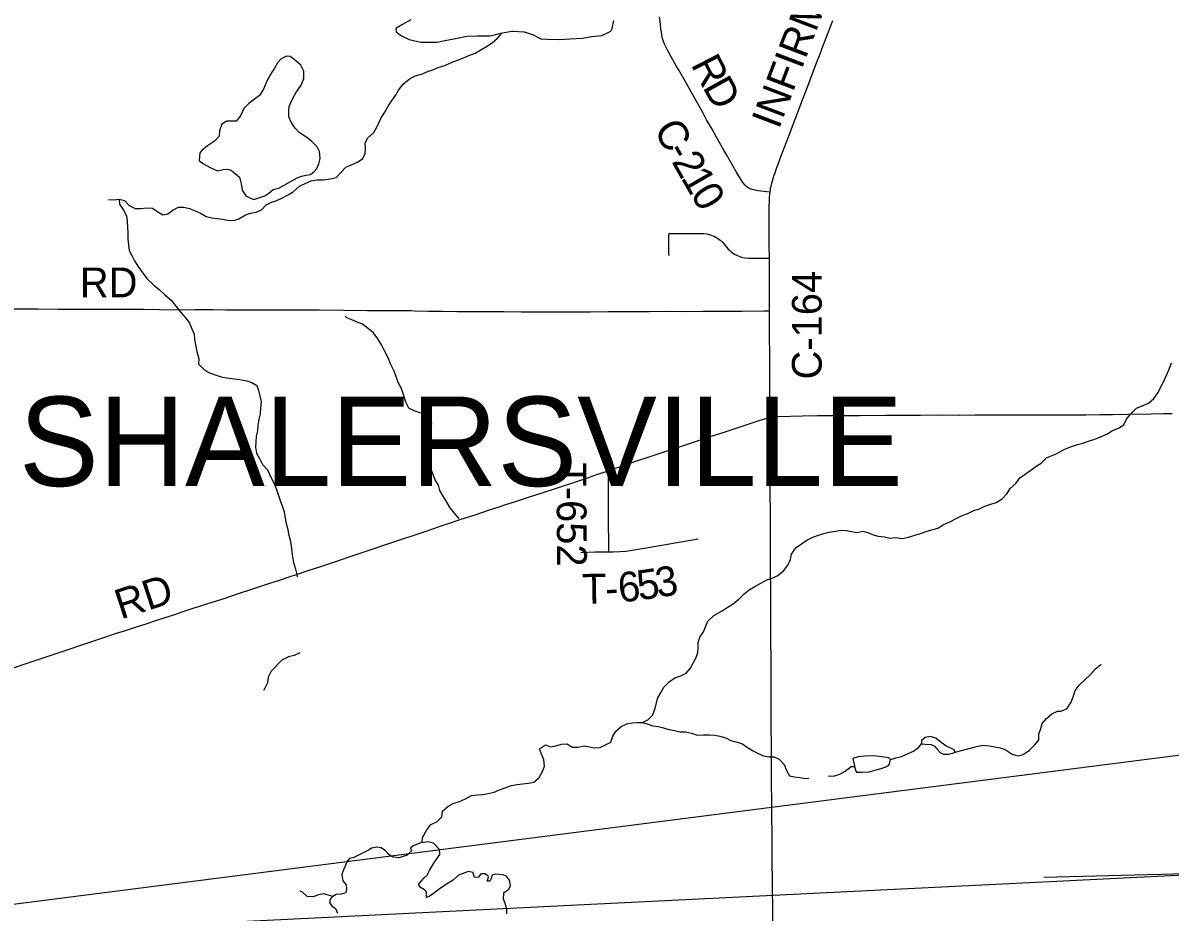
# Model space of a CAD drawing. Extents: x 0 to 34, y 0 to 22.
# Drawn here: x 5.643 to 7.83, y 17.616 to 19.311 of the extents above; entities that cross this region are included whole.
import ezdxf

# ---------------------------------------------------------------- set-up
doc = ezdxf.new("R2010")
doc.units = 0
for name, color, linetype in [('GM_X_County_Road', 7, 'Continuous'), ('GM_X_County_Road_Text', 7, 'Continuous'), ('GM_X_Minor_Lake', 7, 'Continuous'), ('GM_X_Minor_River', 7, 'Continuous'), ('GM_X_Township_Road', 7, 'Continuous'), ('GM_X_Township_Road_Text', 7, 'Continuous'), ('GM_X_Township_Text', 7, 'Continuous'), ('SH_Text', 7, 'Continuous')]:
    doc.layers.add(name, color=color, linetype=linetype)

msp = doc.modelspace()

# ---------------------------------------------------------------- linework, layer by layer
at = {"layer": 'GM_X_County_Road'}
for points in [[(7.0677, 18.9883), (7.0615, 18.9887), (7.0562, 18.9893), (7.0498, 18.9901), (7.0452, 18.9909), (7.0413, 18.9916), (7.0372, 18.9924), (7.0335, 18.9934), (7.0294, 18.9948), (7.026, 18.9967), (7.0234, 18.9984), (7.0201, 19.0014), (7.0159, 19.0065), (7.0123, 19.0115), (7.0091, 19.0167), (7.0043, 19.0251), (6.9859, 19.0574), (6.9795, 19.0685), (6.9719, 19.0818), (6.9655, 19.0933), (6.9569, 19.1084), (6.9467, 19.1264), (6.9391, 19.1403), (6.9235, 19.1684), (6.9141, 19.1853), (6.9025, 19.2057), (6.8932, 19.2219), (6.8882, 19.2303), (6.8822, 19.2406), (6.8725, 19.2579), (6.8663, 19.2705), (6.8642, 19.2756), (6.8628, 19.2811), (6.8612, 19.2877), (6.8603, 19.2931), (6.8595, 19.2991), (6.8585, 19.3083), (6.8569, 19.3227)], [(7.0677, 18.9883), (7.0681, 18.9916), (7.0687, 18.9956), (7.0695, 19), (7.0703, 19.0037), (7.0714, 19.0079), (7.0732, 19.0139), (7.075, 19.0194), (7.077, 19.0254), (7.0792, 19.0314), (7.0818, 19.0385), (7.0849, 19.0469), (7.087, 19.0525), (7.0953, 19.0743), (7.105, 19.0999), (7.1104, 19.1142), (7.1205, 19.1405), (7.1296, 19.1644), (7.1394, 19.1902), (7.1478, 19.2125), (7.1562, 19.2348), (7.1628, 19.2521), (7.1688, 19.268), (7.1755, 19.2854), (7.1872, 19.3154)], [(7.0662, 18.8626), (7.0661, 18.8861), (7.0659, 18.9169), (7.0658, 18.9363), (7.0659, 18.9459), (7.0659, 18.9555), (7.066, 18.9621), (7.0662, 18.9696), (7.0664, 18.9748), (7.0668, 18.9798), (7.0672, 18.9838), (7.0677, 18.9883)], [(7.0665, 18.7619), (7.0664, 18.799), (7.0662, 18.8427), (7.0662, 18.8626)], [(7.0674, 18.5587), (7.0673, 18.583), (7.0671, 18.631), (7.0669, 18.667), (7.0667, 18.7246), (7.0666, 18.7483), (7.0665, 18.7619)], [(6.7591, 18.4569), (6.7668, 18.4599), (6.7827, 18.4653), (6.8138, 18.4759), (6.8371, 18.4835), (6.8616, 18.4917), (6.8949, 18.5027), (6.9256, 18.513), (6.9516, 18.5216), (6.9799, 18.5307), (7.0201, 18.544), (7.0466, 18.5529), (7.0575, 18.5563), (7.0634, 18.5578), (7.0674, 18.5587)], [(7.0674, 18.5587), (7.0716, 18.5595), (7.0771, 18.5602), (7.0835, 18.5607), (7.1291, 18.5621), (7.1576, 18.5623), (7.1812, 18.5624), (7.2384, 18.5626), (7.2888, 18.5631), (7.3149, 18.5632), (7.3547, 18.5633), (7.3969, 18.5634), (7.428, 18.5633), (7.4584, 18.5635), (7.4708, 18.5634), (7.4987, 18.5634), (7.5347, 18.5636), (7.5689, 18.5637), (7.5888, 18.564), (7.6124, 18.564), (7.6509, 18.564), (7.6695, 18.5639), (7.6963, 18.5642), (7.7205, 18.5646), (7.7491, 18.565), (7.7945, 18.5657), (7.8175, 18.5661), (7.8342, 18.5665)], [(7.0731, 17.5947), (7.0727, 17.6245), (7.0726, 17.6352), (7.0725, 17.6478), (7.0722, 17.6785), (7.0719, 17.7095), (7.0715, 17.7689), (7.0712, 17.7939), (7.0709, 17.827), (7.0706, 17.86), (7.0704, 17.8782), (7.0702, 17.912), (7.07, 17.9364), (7.0698, 17.9667), (7.0696, 18.0001), (7.0695, 18.0272), (7.0694, 18.1022), (7.0693, 18.1295), (7.0691, 18.184), (7.0688, 18.232), (7.0686, 18.2645), (7.0685, 18.2999), (7.0682, 18.3495), (7.0681, 18.3774), (7.0679, 18.4134), (7.0678, 18.4367), (7.0677, 18.459), (7.0676, 18.4899), (7.0675, 18.5339), (7.0674, 18.5587)], [(5.6195, 18.0797), (5.653, 18.0911), (5.7214, 18.1139), (5.7652, 18.1282), (5.7858, 18.1352), (5.8235, 18.1478), (5.8347, 18.1515), (5.8577, 18.1589), (5.8778, 18.1654), (5.9003, 18.1727), (5.9346, 18.1839), (5.9428, 18.1866), (5.9698, 18.1955), (5.9715, 18.1961), (5.9739, 18.1968), (5.9786, 18.1984), (5.9844, 18.2002), (5.9862, 18.2008), (5.9919, 18.2024), (6.0038, 18.2063), (6.0268, 18.2138), (6.0539, 18.2228), (6.0793, 18.2311), (6.1122, 18.2421), (6.1322, 18.2487), (6.1487, 18.2542), (6.1683, 18.2604), (6.1872, 18.2666), (6.2131, 18.2753), (6.2378, 18.2836), (6.2689, 18.2942), (6.2954, 18.3031), (6.3485, 18.3207), (6.4081, 18.3406), (6.4268, 18.3472), (6.4404, 18.3518), (6.4562, 18.3572), (6.4727, 18.3627), (6.4905, 18.3684), (6.5052, 18.3732), (6.5182, 18.3774), (6.5305, 18.3818), (6.5511, 18.3886), (6.5658, 18.3936), (6.58, 18.398), (6.6073, 18.4065), (6.635, 18.4158), (6.6587, 18.4235), (6.7011, 18.4375), (6.72, 18.4436), (6.7335, 18.4484), (6.7591, 18.4569)]]:
    msp.add_lwpolyline(points, dxfattribs=at)
at = {"layer": 'GM_X_Minor_Lake'}
for p, q in [((6.1313, 18.9962), (6.166, 19.0155)), ((7.3745, 17.935), (7.3813, 17.932)), ((7.2256, 17.9084), (7.2307, 17.8857))]:
    msp.add_line(p, q, dxfattribs=at)
for points in [[(6.3825, 19.3171), (6.367, 19.3079), (6.3542, 19.3006), (6.355, 19.2942), (6.3649, 19.2863), (6.3797, 19.2796), (6.4017, 19.274), (6.432, 19.2743), (6.4543, 19.2786), (6.4713, 19.2818), (6.4894, 19.2857), (6.5091, 19.2862), (6.5337, 19.2864), (6.5545, 19.2915), (6.5753, 19.2955), (6.5783, 19.2955), (6.5987, 19.2938), (6.6147, 19.2889), (6.6303, 19.2807), (6.6428, 19.2801), (6.667, 19.2791), (6.6855, 19.2808), (6.7101, 19.2821), (6.7275, 19.2853), (6.7468, 19.2869), (6.7577, 19.2923), (6.7638, 19.295), (6.7664, 19.3003), (6.7697, 19.3155)], [(6.166, 19.0155), (6.1743, 19.0189), (6.1834, 19.0205), (6.1913, 19.0221), (6.1981, 19.0275), (6.2037, 19.0332), (6.2071, 19.0423), (6.2096, 19.0526), (6.2084, 19.0659), (6.2038, 19.0749), (6.1942, 19.0851), (6.1843, 19.0926), (6.1695, 19.1023), (6.1619, 19.1106), (6.1542, 19.122), (6.1503, 19.1322), (6.1499, 19.1432), (6.151, 19.1519), (6.1569, 19.1664), (6.1636, 19.1778), (6.1734, 19.1923), (6.1789, 19.2048), (6.1784, 19.2192), (6.1731, 19.2306), (6.1597, 19.2419), (6.1525, 19.2467), (6.1453, 19.2474), (6.1355, 19.2424), (6.1287, 19.2348), (6.1224, 19.2237), (6.1175, 19.2173), (6.1082, 19.2001), (6.1019, 19.1849), (6.094, 19.1723), (6.0846, 19.1658), (6.0737, 19.1574), (6.0643, 19.1478), (6.058, 19.1337), (6.0497, 19.1238), (6.0316, 19.1237), (6.0225, 19.1179), (6.0181, 19.105), (6.017, 19.0951), (6.0084, 19.0856), (5.9952, 19.0764), (5.9843, 19.0679), (5.9806, 19.0634), (5.9788, 19.0489), (5.986, 19.0429), (6.0016, 19.0347), (6.0141, 19.0287), (6.0247, 19.0318), (6.0334, 19.0319), (6.0402, 19.0304), (6.0448, 19.0267), (6.0559, 19.0169), (6.0594, 19.0044), (6.061, 18.9919), (6.0686, 18.9806), (6.0834, 18.9746), (6.1042, 18.9812), (6.1117, 18.9862), (6.1204, 18.9931), (6.1313, 18.9962)], [(7.3813, 17.932), (7.3855, 17.9267), (7.3924, 17.9195), (7.3985, 17.9166), (7.4072, 17.917), (7.4159, 17.9186), (7.4204, 17.9205), (7.4185, 17.9251), (7.4029, 17.9325), (7.3941, 17.9389), (7.3839, 17.9472), (7.3732, 17.9501), (7.363, 17.9485), (7.3563, 17.9428), (7.3563, 17.9363), (7.3635, 17.9356), (7.3745, 17.935)], [(7.2307, 17.8857), (7.2322, 17.8827), (7.2349, 17.8823), (7.2417, 17.8824), (7.2564, 17.8832), (7.2697, 17.8868), (7.2791, 17.8895), (7.2885, 17.8926), (7.2934, 17.8953), (7.2953, 17.8979), (7.2975, 17.9063), (7.2941, 17.9097), (7.2801, 17.9119), (7.2645, 17.9136), (7.2479, 17.9131), (7.2358, 17.9115), (7.2256, 17.9084)], [(6.3444, 17.7223), (6.3395, 17.7268), (6.3341, 17.7321), (6.3261, 17.7381), (6.3182, 17.7392), (6.3076, 17.7376), (6.3034, 17.7345), (6.2966, 17.731), (6.2895, 17.7276), (6.2737, 17.7195), (6.2657, 17.7175), (6.2616, 17.7133), (6.2586, 17.7065), (6.2542, 17.6962), (6.2512, 17.6874), (6.252, 17.6829), (6.2528, 17.6753), (6.2593, 17.6678), (6.2601, 17.6598), (6.259, 17.6526), (6.25, 17.6495), (6.2405, 17.6494), (6.2341, 17.6456), (6.2288, 17.6403), (6.2274, 17.6334), (6.232, 17.6274), (6.2392, 17.6225), (6.2431, 17.6138)], [(6.5655, 17.6125), (6.5658, 17.6212), (6.5616, 17.6341), (6.5596, 17.6401), (6.5599, 17.6515), (6.561, 17.6538), (6.5686, 17.6588), (6.5727, 17.6656), (6.5707, 17.6762), (6.565, 17.6842), (6.5578, 17.6868), (6.5449, 17.6882), (6.537, 17.6862), (6.5362, 17.6809), (6.5336, 17.6748), (6.5283, 17.6744), (6.5309, 17.6824), (6.5298, 17.6846), (6.5237, 17.6888), (6.5173, 17.6883), (6.515, 17.6864), (6.5116, 17.6822), (6.5041, 17.6814), (6.5025, 17.6856), (6.5017, 17.6913), (6.4919, 17.6931), (6.4858, 17.6904), (6.4734, 17.6857), (6.4632, 17.6762), (6.4504, 17.6689), (6.435, 17.6581), (6.4259, 17.6512), (6.4173, 17.6455), (6.4124, 17.6432), (6.4127, 17.6545), (6.4089, 17.6579), (6.4013, 17.6624), (6.3974, 17.6681), (6.4076, 17.6803), (6.4139, 17.686), (6.418, 17.6948), (6.4251, 17.707), (6.4322, 17.7173), (6.4379, 17.7253), (6.437, 17.7348), (6.426, 17.7468), (6.4157, 17.7498), (6.4017, 17.7478), (6.3874, 17.742), (6.3818, 17.7374), (6.3837, 17.7325), (6.3754, 17.7244), (6.366, 17.7209), (6.3592, 17.719), (6.3493, 17.7204), (6.3444, 17.7223)]]:
    msp.add_lwpolyline(points, dxfattribs=at)
at = {"layer": 'GM_X_Minor_River'}
for points in [[(5.806, 18.9744), (5.8162, 18.9737), (5.8264, 18.9749), (5.8367, 18.9724), (5.8458, 18.9626), (5.8572, 18.957), (5.8678, 18.957), (5.8792, 18.9586), (5.8898, 18.958), (5.9001, 18.9508), (5.9096, 18.9448), (5.9194, 18.9472), (5.9292, 18.9537), (5.9397, 18.9599), (5.9496, 18.9599), (5.9609, 18.957), (5.9704, 18.9533), (5.9814, 18.9484), (5.9925, 18.9417), (6.0035, 18.9395), (6.0133, 18.9381), (6.0235, 18.937), (6.0334, 18.9348), (6.0451, 18.9341), (6.055, 18.9372), (6.0674, 18.9449), (6.0772, 18.948), (6.0878, 18.9504), (6.098, 18.9543), (6.107, 18.9642), (6.1172, 18.9692), (6.127, 18.9723), (6.1379, 18.9773), (6.1477, 18.9827), (6.1583, 18.9892), (6.1707, 18.9996), (6.1827, 19.0057), (6.1925, 19.0096), (6.2035, 19.0116), (6.2164, 19.0117), (6.2292, 19.0137), (6.2406, 19.016), (6.2499, 19.0263), (6.259, 19.0359), (6.2707, 19.0409), (6.2812, 19.0452), (6.2914, 19.0524), (6.2958, 19.062), (6.2965, 19.0715), (6.2953, 19.0821), (6.3005, 19.0916), (6.3118, 19.1023), (6.3185, 19.1137), (6.3264, 19.1301), (6.3331, 19.1408), (6.3391, 19.1507), (6.3454, 19.161), (6.3533, 19.1724), (6.3593, 19.1827), (6.3679, 19.1945), (6.3795, 19.2037), (6.3912, 19.2099), (6.4048, 19.2141), (6.4146, 19.2184), (6.4248, 19.2215), (6.435, 19.2261), (6.4475, 19.23), (6.458, 19.2347), (6.4716, 19.2397), (6.4818, 19.2439), (6.4931, 19.2486), (6.5052, 19.2532), (6.5161, 19.2597), (6.5271, 19.2659), (6.5376, 19.2732), (6.5481, 19.2816), (6.5567, 19.2919)], [(5.8264, 18.9749), (5.8269, 18.9655), (5.8349, 18.9541), (5.8403, 18.9432), (5.8415, 18.9326), (5.8424, 18.9216), (5.8428, 18.911), (5.8433, 18.8988), (5.8445, 18.8878), (5.8457, 18.8772), (5.8504, 18.8674), (5.8557, 18.8576), (5.8634, 18.8455), (5.8707, 18.8357), (5.8791, 18.8236), (5.8924, 18.8112), (5.9027, 18.8029), (5.9138, 18.7928), (5.926, 18.7823), (5.9355, 18.7702), (5.9447, 18.7585), (5.9538, 18.7483), (5.9604, 18.7385), (5.965, 18.7279), (5.9696, 18.7177), (5.9704, 18.7071), (5.9744, 18.6844), (5.9783, 18.6708), (5.9776, 18.6601), (5.9879, 18.6507), (5.9978, 18.6447), (6.0099, 18.6399), (6.0209, 18.6362), (6.0312, 18.634), (6.0463, 18.6322), (6.0562, 18.6308), (6.0698, 18.6286), (6.0793, 18.6253), (6.0892, 18.6196), (6.0923, 18.6098), (6.0946, 18.6), (6.097, 18.5886), (6.0963, 18.5765), (6.0953, 18.5658), (6.0931, 18.5556), (6.0909, 18.5442), (6.0902, 18.5335), (6.0877, 18.5229), (6.087, 18.5119), (6.0867, 18.502), (6.0883, 18.4907), (6.0941, 18.4805), (6.0998, 18.4688), (6.1094, 18.4586), (6.1155, 18.445), (6.1209, 18.4352), (6.1263, 18.4212), (6.1302, 18.4102), (6.1333, 18.4004), (6.1379, 18.3886), (6.141, 18.3788), (6.1442, 18.3591), (6.1473, 18.3477), (6.1501, 18.3345), (6.1524, 18.3247), (6.1544, 18.314), (6.156, 18.3034), (6.1568, 18.2928), (6.1592, 18.2822), (6.1627, 18.2694), (6.165, 18.2591), (6.1658, 18.255)], [(6.4746, 18.3654), (6.465, 18.3767), (6.4574, 18.3865), (6.4512, 18.3975), (6.4443, 18.4088), (6.4382, 18.4194), (6.4351, 18.4296), (6.4289, 18.4398), (6.4251, 18.4496), (6.4212, 18.4598), (6.4143, 18.4704), (6.4078, 18.4814), (6.4055, 18.4923), (6.408, 18.503), (6.4117, 18.5132), (6.4169, 18.5247), (6.4195, 18.5364), (6.4228, 18.5471), (6.4186, 18.5573), (6.4098, 18.5671), (6.3996, 18.5674), (6.3889, 18.5711), (6.3787, 18.5767), (6.3733, 18.5877), (6.3683, 18.6047), (6.3644, 18.6149), (6.3586, 18.6255), (6.3544, 18.6365), (6.3501, 18.6482), (6.3436, 18.6607), (6.3397, 18.6724), (6.3332, 18.6845), (6.327, 18.6973), (6.3198, 18.7086), (6.3113, 18.72), (6.3018, 18.7278), (6.2908, 18.7365), (6.2802, 18.7402), (6.2703, 18.7447), (6.2608, 18.7484), (6.2574, 18.7518)], [(7.6132, 18.4891), (7.6286, 18.4973), (7.6407, 18.5027), (7.6535, 18.507), (7.6641, 18.5094), (7.6765, 18.5142), (7.6867, 18.5173), (7.6973, 18.5216), (7.7097, 18.5267), (7.7203, 18.5336), (7.7319, 18.5383), (7.7421, 18.5449), (7.7469, 18.5552), (7.7547, 18.5652), (7.7664, 18.5763), (7.7773, 18.581), (7.789, 18.5861), (7.7995, 18.5946), (7.8077, 18.6061), (7.8129, 18.6171), (7.8181, 18.6278), (7.824, 18.6408), (7.8284, 18.6507), (7.8332, 18.6629)], [(7.2958, 18.3288), (7.3075, 18.3297), (7.3204, 18.3279), (7.3313, 18.3302), (7.3438, 18.3341), (7.3547, 18.3372), (7.3649, 18.3415), (7.3763, 18.3446), (7.3872, 18.3477), (7.3978, 18.3539), (7.4102, 18.3597), (7.4223, 18.3658), (7.434, 18.3716), (7.4449, 18.3759), (7.4558, 18.3816), (7.4668, 18.3847), (7.477, 18.3898), (7.4868, 18.3925), (7.4989, 18.3967), (7.5098, 18.4033), (7.5199, 18.414), (7.5255, 18.4235), (7.5364, 18.4331), (7.5439, 18.4437), (7.5541, 18.4507), (7.5646, 18.4583), (7.5748, 18.4656), (7.5846, 18.4717), (7.5947, 18.4817), (7.6132, 18.4891)], [(6.4044, 17.7481), (6.4051, 17.758), (6.4133, 17.7725), (6.4211, 17.7828), (6.4321, 17.7874), (6.4418, 17.7974), (6.4429, 17.808), (6.453, 17.8172), (6.4632, 17.8226), (6.4753, 17.8265), (6.487, 17.8315), (6.4983, 17.8376), (6.5097, 17.8392), (6.5195, 17.8397), (6.5304, 17.8417), (6.5418, 17.8444), (6.552, 17.849), (6.5746, 17.8568), (6.5856, 17.8588), (6.5958, 17.8604), (6.6067, 17.8612), (6.617, 17.8632), (6.6271, 17.872), (6.6334, 17.8838), (6.6375, 17.8937), (6.6363, 17.9058), (6.6321, 17.9164), (6.6278, 17.9266), (6.6395, 17.9343), (6.649, 17.9306), (6.6592, 17.9329), (6.6698, 17.9357), (6.6803, 17.9365), (6.691, 17.9301), (6.7008, 17.9302), (6.7129, 17.9326), (6.7232, 17.9304), (6.7326, 17.9286), (6.7436, 17.9294), (6.764, 17.9398), (6.768, 17.9508), (6.7733, 17.9603), (6.7834, 17.9695), (6.7944, 17.9745), (6.8046, 17.9765), (6.8144, 17.9773), (6.8246, 17.9774), (6.8344, 17.9824), (6.8442, 17.992), (6.8482, 18.0045), (6.8534, 18.0243), (6.8601, 18.035), (6.865, 18.0445), (6.8751, 18.0548), (6.886, 18.0621), (6.8974, 18.066), (6.9075, 18.071), (6.9158, 18.0809), (6.9214, 18.0912), (6.9266, 18.1011), (6.9299, 18.1106), (6.9302, 18.1205), (6.9305, 18.1299), (6.9335, 18.1398), (6.9406, 18.1501), (6.9443, 18.1596), (6.9488, 18.1703), (6.9604, 18.181), (6.9763, 18.1898), (6.9861, 18.1964), (6.997, 18.2033), (7.0086, 18.2128), (7.018, 18.2224), (7.0278, 18.2301), (7.0387, 18.2362), (7.05, 18.2427), (7.0613, 18.2489), (7.0719, 18.2524), (7.0821, 18.2574), (7.0938, 18.267), (7.1016, 18.2769), (7.1065, 18.2876), (7.1083, 18.2982), (7.1176, 18.3108), (7.1274, 18.3177), (7.1376, 18.3246), (7.1478, 18.3296), (7.158, 18.3338), (7.17, 18.3377), (7.1799, 18.3397), (7.1927, 18.3421), (7.2025, 18.344), (7.2124, 18.343), (7.223, 18.3415), (7.2329, 18.3393), (7.2442, 18.3421), (7.2537, 18.3395), (7.2632, 18.3354), (7.273, 18.3324), (7.2855, 18.3314), (7.2958, 18.3288)], [(6.1711, 18.1097), (6.1605, 18.1047), (6.1496, 18.102), (6.1368, 18.0958), (6.1165, 18.0752), (6.1109, 18.0634), (6.1091, 18.0527), (6.1046, 18.0425), (6.102, 18.0383)], [(7.6217, 17.999), (7.6337, 18.0033), (7.6416, 18.0159), (7.646, 18.0281), (7.6493, 18.038), (7.6571, 18.048), (7.6668, 18.058), (7.6788, 18.0683), (7.6882, 18.0791), (7.698, 18.0876), (7.698, 18.0868)], [(7.4204, 17.9205), (7.4638, 17.9322), (7.4748, 17.9338), (7.4858, 17.9328), (7.496, 17.9306), (7.5066, 17.9288), (7.5161, 17.9254), (7.5291, 17.9164), (7.5397, 17.9138), (7.5499, 17.9162), (7.5623, 17.9243), (7.5724, 17.9346), (7.5799, 17.9441), (7.5799, 17.9551), (7.5839, 17.9654), (7.5865, 17.9753), (7.5948, 17.9848), (7.6045, 17.9936), (7.6155, 17.999), (7.6217, 17.999)], [(6.8246, 17.9774), (6.8349, 17.9737), (6.8443, 17.9707), (6.8542, 17.9693), (6.8644, 17.9667), (6.8747, 17.9638), (6.8853, 17.962), (6.8955, 17.959), (6.9061, 17.9595), (6.9175, 17.9569), (6.9285, 17.9532), (6.9406, 17.9537), (6.952, 17.9537), (6.9622, 17.9527), (6.9717, 17.9509), (6.983, 17.9479), (6.9929, 17.9427), (7.0024, 17.9401), (7.0138, 17.9368), (7.0248, 17.9296), (7.0355, 17.9229), (7.045, 17.9177), (7.0552, 17.9136), (7.0655, 17.9117), (7.0753, 17.9114), (7.0848, 17.9073), (7.0943, 17.8972), (7.099, 17.8855), (7.1047, 17.8756), (7.1142, 17.8734), (7.1248, 17.8724), (7.1347, 17.8706), (7.1418, 17.871)], [(7.2975, 17.9063), (7.3073, 17.9098), (7.3183, 17.9125), (7.3307, 17.9179), (7.3409, 17.9222), (7.3511, 17.9299), (7.3563, 17.9363)], [(7.1785, 17.8751), (7.1884, 17.8748), (7.2008, 17.8786), (7.2106, 17.884), (7.2219, 17.8932), (7.229, 17.8933)], [(6.2341, 17.6456), (6.2167, 17.6504), (6.2065, 17.6484), (6.1966, 17.6449), (6.1853, 17.6456), (6.1758, 17.6535), (6.1716, 17.6554)]]:
    msp.add_lwpolyline(points, dxfattribs=at)
at = {"layer": 'GM_X_Township_Road'}
for points in [[(6.8749, 18.8676), (6.8748, 18.8705), (6.8748, 18.8831), (6.8747, 18.8912), (6.8748, 18.8996), (6.8747, 18.9063), (6.875, 18.9093)], [(6.875, 18.9093), (6.8776, 18.9095), (6.8799, 18.9094), (6.8923, 18.9096), (6.9001, 18.9096), (6.9101, 18.9097), (6.9188, 18.9096), (6.9312, 18.9097), (6.9362, 18.9096), (6.9416, 18.9093), (6.9472, 18.9086), (6.9509, 18.9076), (6.9541, 18.9067), (6.9565, 18.9058), (6.9608, 18.9041), (6.9641, 18.9024), (6.9701, 18.8985), (6.9725, 18.8967), (6.9741, 18.8952), (6.9768, 18.8927), (6.9795, 18.8897), (6.983, 18.8855), (6.9879, 18.8799), (6.9901, 18.8776), (6.9937, 18.8746), (6.9962, 18.8725), (7.0008, 18.8697), (7.0031, 18.8685), (7.0065, 18.8668), (7.0132, 18.8646), (7.0156, 18.864), (7.0203, 18.8631), (7.0256, 18.8627), (7.0306, 18.8626), (7.0419, 18.8626), (7.0537, 18.8626), (7.0619, 18.8626), (7.0651, 18.8626), (7.0662, 18.8626)], [(5.6189, 18.7658), (5.6481, 18.7658), (5.6724, 18.7658), (5.7102, 18.7655), (5.7251, 18.7655), (5.7387, 18.7654), (5.7604, 18.7655), (5.7865, 18.7653), (5.8189, 18.7653), (5.8524, 18.7655), (5.8729, 18.7651), (5.9034, 18.7648), (5.9469, 18.7642), (5.9711, 18.7644), (6.0059, 18.7644), (6.0302, 18.7641), (6.0824, 18.7639), (6.1178, 18.7642), (6.2079, 18.7638), (6.2552, 18.7633), (6.2999, 18.7629), (6.3217, 18.7626), (6.3627, 18.7626), (6.3838, 18.7625), (6.39, 18.7623), (6.4161, 18.7616), (6.4422, 18.7612), (6.4701, 18.7608), (6.4965, 18.7607), (6.5297, 18.7607), (6.5601, 18.7607), (6.593, 18.7604), (6.6303, 18.7601), (6.6613, 18.7603), (6.6926, 18.7603), (6.7254, 18.7603), (6.7586, 18.7608), (6.7919, 18.7609), (6.8368, 18.7608), (6.8726, 18.7611), (6.9036, 18.7608), (6.9393, 18.7613), (6.971, 18.7613), (6.984, 18.7613), (6.9952, 18.7613), (7.0138, 18.7612), (7.0563, 18.7618), (7.0665, 18.7619)], [(6.7601, 18.3025), (6.76, 18.3102), (6.7599, 18.3151), (6.7598, 18.363), (6.7596, 18.4009), (6.7595, 18.4357), (6.7591, 18.4569)], [(6.7601, 18.3025), (6.7683, 18.3027), (6.7819, 18.3031), (6.7925, 18.304), (6.8048, 18.3059), (6.8648, 18.3161), (6.8936, 18.3211), (6.9194, 18.3253), (6.9305, 18.3271)], [(6.7067, 18.3015), (6.7341, 18.3022), (6.7601, 18.3025)], [(7.5895, 17.6821), (7.7873, 17.687), (7.814, 17.6878), (7.9048, 17.6903), (7.9345, 17.6906)]]:
    msp.add_lwpolyline(points, dxfattribs=at)
at = {"layer": 'SH_Text'}
msp.add_lwpolyline([(9.4006, 18.113), (4.9378, 17.5422), (9.4006, 17.763)], close=True, dxfattribs=at)

# ---------------------------------------------------------------- texts
at = {"layer": 'GM_X_County_Road_Text'}
for s, height, rotation, p in [('INFIRMARY', 0.05682, 69.1728, (7.0842, 19.1066)), ('R', 0.0568, 297.2737, (6.9158, 19.2319)), ('D', 0.0568, 299.0802, (6.9381, 19.1887)), ('C', 0.0568, 299.3746, (6.8447, 19.1078)), ('-', 0.0568, 299.4117, (6.8676, 19.0671)), ('2', 0.0568, 299.5001, (6.8791, 19.0467)), ('1', 0.0568, 299.8827, (6.8966, 19.0159)), ('0', 0.0568, 301.1303, (6.9147, 18.9844)), ('C-164', 0.05682, 90, (7.1661, 18.6312)), ('RD', 0.05682, 18.1207, (5.8297, 18.1733))]:
    msp.add_text(s, height=height, rotation=rotation, dxfattribs=at).set_placement(p)
at = {"layer": 'GM_X_Township_Road_Text'}
for s, height, rotation, p in [('RD', 0.05682, 0, (5.7516, 18.7878)), ('T-652', 0.05682, 270.2823, (6.6605, 18.4728)), ('6', 0.0568, 5.8438, (6.7805, 18.2059)), ('5', 0.0568, 8.2952, (6.8179, 18.2098)), ('3', 0.0568, 9.228, (6.8536, 18.215)), ('T', 0.0568, 0.9858, (6.7095, 18.2035)), ('-', 0.0568, 3.3098, (6.7545, 18.2043))]:
    msp.add_text(s, height=height, rotation=rotation, dxfattribs=at).set_placement(p)
at = {"layer": 'GM_X_Township_Text'}
msp.add_text('SHALERSVILLE', height=0.170455, rotation=0, dxfattribs=at).set_placement((5.6356, 18.4279))

doc.saveas('drawing.dxf')
